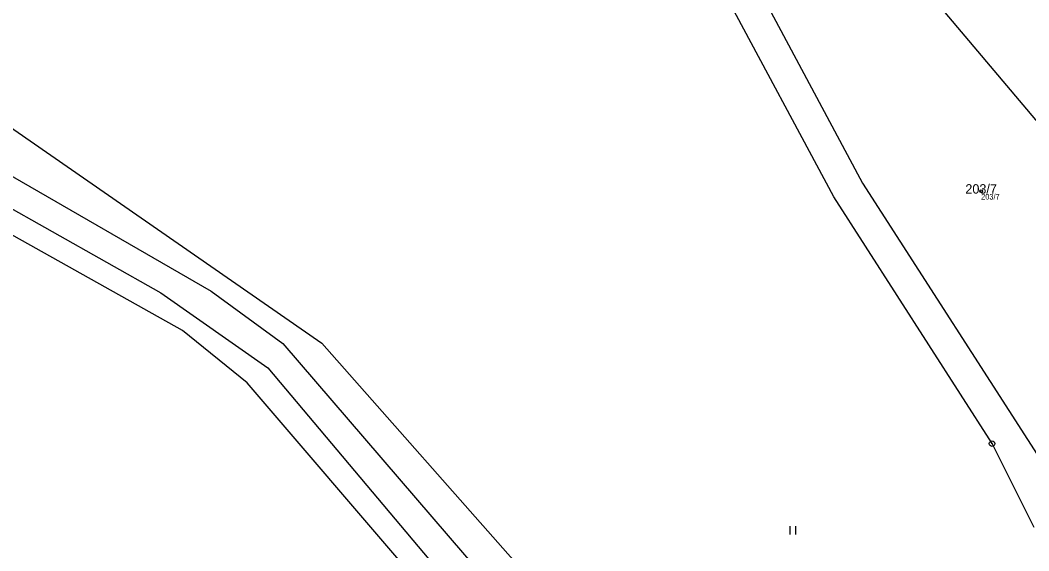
# Model space of a CAD drawing. Extents: x -867966 to -864255, y -1043242 to -1041327.
# Drawn here: x -865512.1 to -865330.3, y -1042022 to -1041926.4 of the extents above; entities that cross this region are included whole.
import ezdxf

# ---------------------------------------------------------------- set-up
doc = ezdxf.new("R2010")
doc.units = 0
for name, color, linetype in [('Definiční body', 7, 'Continuous'), ('Hranice parcel', 7, 'Continuous'), ('Parcelní čísla', 7, 'Continuous'), ('Značky bodu BP', 7, 'Continuous'), ('Značky kultur', 7, 'Continuous')]:
    doc.layers.add(name, color=color, linetype=linetype)

msp = doc.modelspace()

# ---------------------------------------------------------------- linework, layer by layer
at = {"layer": 'Definiční body'}
msp.add_circle((-865338.91, -1041957.23), 0.25, dxfattribs=at)
at = {"layer": 'Hranice parcel'}
for p, q in [((-865358, -1041910.07), (-865292.46, -1041987.89)), ((-865557.23, -1041915.66), (-865457.75, -1041984.58)), ((-865380.56, -1041917.93), (-865360.32, -1041955.76)), ((-865573.59, -1041919.93), (-865477.7, -1041975.25)), ((-865365.49, -1041958.24), (-865386.06, -1041919.8)), ((-865531.46, -1041950.38), (-865486.81, -1041975.51)), ((-865482.87, -1041982.33), (-865538.29, -1041951.28)), ((-865360.32, -1041955.76), (-865327.21, -1042007.17)), ((-865336.93, -1042002.71), (-865365.49, -1041958.24)), ((-865486.81, -1041975.51), (-865467.47, -1041989.05)), ((-865477.7, -1041975.25), (-865464.77, -1041984.64)), ((-865471.2, -1041991.73), (-865482.87, -1041982.33)), ((-865464.77, -1041984.64), (-865418.27, -1042038.75)), ((-865457.75, -1041984.58), (-865355.47, -1042100.41)), ((-865467.47, -1041989.05), (-865419.94, -1042045.55)), ((-865425.81, -1042044.73), (-865471.2, -1041991.73)), ((-865329.36, -1042017.79), (-865336.93, -1042002.71))]:
    msp.add_line(p, q, dxfattribs=at)
at = {"layer": 'Značky bodu BP'}
for radius in [0.5, 0.0303]:
    msp.add_circle((-865336.93, -1042002.71), radius, dxfattribs=at)
at = {"layer": 'Značky kultur'}
for p, q in [((-865373.34, -1042019.09), (-865373.34, -1042017.59)), ((-865372.34, -1042019.09), (-865372.34, -1042017.59))]:
    msp.add_line(p, q, dxfattribs=at)

# ---------------------------------------------------------------- texts
at = {"layer": 'Definiční body'}
msp.add_text('203/7', height=1, dxfattribs=at).set_placement((-865338.91, -1041958.72))
at = {"layer": 'Parcelní čísla'}
msp.add_text('203/7', height=1.7, dxfattribs=at).set_placement((-865341.75, -1041957.66))

doc.saveas('drawing.dxf')
